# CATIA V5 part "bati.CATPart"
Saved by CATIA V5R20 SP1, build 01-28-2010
Part number: bati
Publications: "Plan.1", "A", "E", "axe_bati_1", "axe_bati_2", "OB", "batidroit", "batigauche", "Droite.1", "Droite.2", "Droite.3"
Bounding box of the stored display mesh (mm): x -10 to 0, y -699.989 to 0, z -280 to 237.179
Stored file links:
  C:\Users\patrice\Desktop\IFMa\Semestre 3\IAO\projet iao\iao\bati.CATPart
  C:\Users\patrice\Desktop\IFMa\Semestre 3\IAO\projet iao\iao\skl_iao_755.CATProduct
  C:\Users\patrice\Desktop\IFMa\Semestre 3\IAO\projet iao\iao\skl_general.CATPart
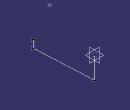
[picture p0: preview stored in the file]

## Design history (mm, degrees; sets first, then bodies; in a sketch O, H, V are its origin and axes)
Parameters
  LENGTH = 10 mm
External parameters (linked from other documents)
  External.AC = 200 mm
Set1
  Plane1: linked copy from another document
  Point1 "A": linked copy from another document
  DatumPoint1 "E": linked copy from another document
  DatumCurve1 "OB": linked copy from another document
  DatumPoint2 "O": linked copy from another document
Set2
  Plane2: type Offset, RefPlane Plane1, Offset 0
  Point2 "A": (0, 0, 0), relative to Point1
  Point3 "E": (0, 0, 0), relative to DatumPoint1
  Point4 "batidroit": (0, 0, -246 {= -1.23*External.AC})
  Point5 "batigauche": (0, 0, -80 {= -0.4*External.AC}), relative to DatumPoint1
  Line1: type PtPt, FirstPoint Point5, SecondPoint Point4
  Line2: type PtPt, FirstPoint Point2, SecondPoint Point4
  Line3: type PtPt, FirstPoint Point3, SecondPoint Point5
  Line4 "axe_bati_1": type Normal, RefPoint Point2, RefSkin Plane2, Start 0, End 10
  Line5 "axe_bati_2": type Normal, RefPoint Point3, RefSkin Plane2, Start 0, End 10
  Circle1 "OB": type CtrRad, Start 0, End 180, Center DatumPoint2, Support Plane1, Radius 272 {= 1.36*External.AC}, FirstDirection (0, 1, 0)
Body1 (main body)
